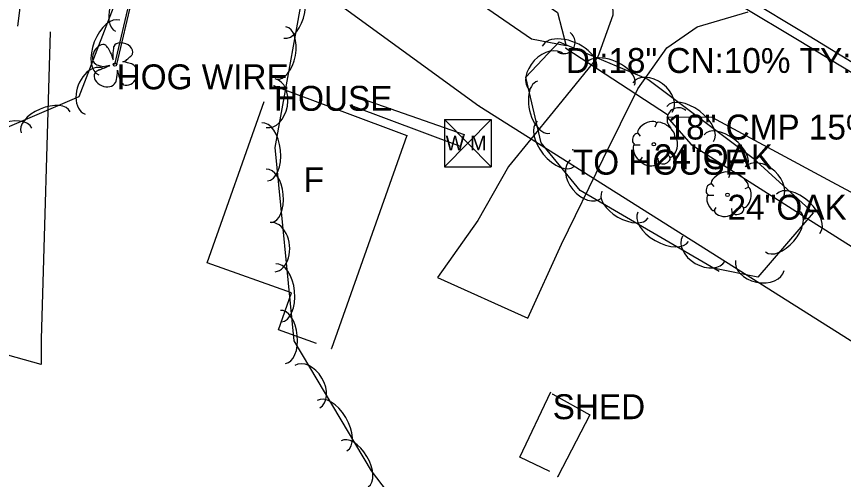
# Model space of a CAD drawing. Extents: x 1441650 to 1491889, y 345904 to 358319.
# Drawn here: x 1445119.8 to 1445285.8, y 354726 to 354818.8 of the extents above; entities that cross this region are included whole.
import ezdxf

# ---------------------------------------------------------------- set-up
doc = ezdxf.new("R2010")
doc.units = 0
for name, color, linetype in [('S_BUILDING', 7, 'Continuous'), ('S_BUILDING_ANNOT', 7, 'Continuous'), ('S_CROSS_DRAIN', 7, 'Continuous'), ('S_CROSS_DRAIN_ANNOT', 7, 'Continuous'), ('S_DITCHLINE', 7, 'Continuous'), ('S_DRG_PT_SYM', 7, 'Continuous'), ('S_EDGE_PAVEMENT', 7, 'Continuous'), ('S_FENCE', 7, 'Continuous'), ('S_FENCE_ANNOT', 7, 'Continuous'), ('S_GRAVEL_ROAD', 7, 'Continuous'), ('S_MSC_PT_SYM', 7, 'Continuous'), ('S_PARKING', 7, 'Continuous'), ('S_SHOULDER', 7, 'Continuous'), ('S_SIDEWALK', 7, 'Continuous'), ('S_STR_PT_SYM', 7, 'Continuous'), ('S_SURVEY_TEXT_ANNOT', 7, 'Continuous'), ('S_TREE', 7, 'Continuous'), ('S_TREE_ANNOT', 7, 'Continuous'), ('S_UTL_PT_SYM', 7, 'Continuous'), ('S_WATER_UTILITIES', 7, 'Continuous')]:
    doc.layers.add(name, color=color, linetype=linetype)

msp = doc.modelspace()

# ---------------------------------------------------------------- linework, layer by layer
at = {"layer": 'S_BUILDING'}
for p, q in [((1445171.46, 354804.91), (1445198.16, 354794.96)), ((1445198.16, 354794.96), (1445183.03, 354752.26)), ((1445227.42, 354743.05), (1445234.89, 354738.9)), ((1445234.89, 354738.9), (1445228.42, 354726.52))]:
    msp.add_line(p, q, dxfattribs=at)
for points in [[(1445179.98, 354753.26), (1445172.35, 354755.96), (1445174.99, 354763.4), (1445158.04, 354769.4), (1445169.51, 354801.81)], [(1445226.82, 354727.56), (1445220.79, 354730.44), (1445227.05, 354743.55)]]:
    msp.add_lwpolyline(points, dxfattribs=at)
at = {"layer": 'S_CROSS_DRAIN'}
msp.add_line((1445230.06, 354812.5), (1445250.49, 354799.15), dxfattribs=at)
for centre, start, end in [((1445229.64, 354813.68), 236.3419, 56.6711), ((1445252.68, 354798.21), 50.5486, 230.8777)]:
    msp.add_arc(centre, 2.3, start, end, dxfattribs=at)
at = {"layer": 'S_DITCHLINE'}
msp.add_lwpolyline([(1445133.69, 354878.31), (1445145.12, 354876.22), (1445156.65, 354868.46), (1445168.18, 354860.69), (1445179.71, 354852.93), (1445191.24, 354845.17), (1445209.83, 354832.39), (1445228.41, 354819.61), (1445230.13, 354812.91), (1445223.16, 354814.25), (1445205.4, 354826.54), (1445187.64, 354838.83), (1445175.09, 354847.2), (1445162.53, 354855.58), (1445149.98, 354863.95), (1445137.42, 354872.33)], close=True, dxfattribs=at)
for points in [[(1445250.37, 354798.73), (1445259.4, 354798.62), (1445271.46, 354792.13), (1445283.51, 354785.64), (1445295.57, 354779.15), (1445307.62, 354772.66), (1445328.21, 354760.56), (1445348.8, 354748.46), (1445369.38, 354736.36), (1445389.97, 354724.26), (1445403.57, 354716.68), (1445417.17, 354709.1), (1445430.78, 354701.52), (1445444.38, 354693.94), (1445450.39, 354687.52), (1445454.25, 354683.19)], [(1445250.37, 354798.73), (1445255.23, 354793.12), (1445266.85, 354785.74), (1445278.47, 354778.37), (1445290.09, 354771), (1445301.71, 354763.63), (1445322.84, 354752.21), (1445343.98, 354740.8), (1445365.12, 354729.38), (1445386.26, 354717.97), (1445400.04, 354710.57), (1445413.83, 354703.16), (1445427.62, 354695.76), (1445441.41, 354688.36), (1445449.06, 354684.91), (1445454.1, 354683.1)]]:
    msp.add_lwpolyline(points, dxfattribs=at)
at = {"layer": 'S_DRG_PT_SYM'}
for points in [[(1445230.06, 354812.5), (1445230.06, 354812.55), (1445230.06, 354812.5), (1445230.01, 354812.5), (1445230.06, 354812.5), (1445230.06, 354812.45), (1445230.06, 354812.5), (1445230.11, 354812.5)], [(1445250.49, 354799.15), (1445250.49, 354799.2), (1445250.49, 354799.15), (1445250.44, 354799.15), (1445250.49, 354799.15), (1445250.49, 354799.1), (1445250.49, 354799.15), (1445250.54, 354799.15)]]:
    msp.add_lwpolyline(points, dxfattribs=at)
at = {"layer": 'S_EDGE_PAVEMENT'}
msp.add_lwpolyline([(1445104.48, 354931.44), (1445117.54, 354922.02), (1445130.6, 354912.6), (1445144.39, 354902.99), (1445158.18, 354893.39), (1445171.35, 354884.38), (1445184.53, 354875.37), (1445198.09, 354866.37), (1445211.64, 354857.38), (1445224.35, 354849.14), (1445237.06, 354840.89), (1445251.76, 354831.71), (1445266.45, 354822.53), (1445278.03, 354815.47), (1445289.61, 354808.41)], dxfattribs=at)
at = {"layer": 'S_FENCE'}
msp.add_line((1445139.86, 354809.22), (1445149.39, 354849.44), dxfattribs=at)
at = {"layer": 'S_GRAVEL_ROAD'}
for points in [[(1445145.25, 354898.26), (1445134.77, 354893.19), (1445128.47, 354882.68), (1445125.02, 354867.07), (1445123.61, 354846.52), (1445123.67, 354846.62), (1445121.82, 354831.77), (1445119.97, 354816.92)], [(1445240.23, 354836.51), (1445239.23, 354827.85), (1445239.49, 354819.07), (1445236.48, 354810.72), (1445227.52, 354799.71), (1445218.56, 354788.71), (1445212.4, 354777.92), (1445204.27, 354766.46), (1445222.43, 354758.3), (1445229.22, 354773.13), (1445237.54, 354790.26), (1445244.54, 354804.35), (1445250.33, 354812.56), (1445256.45, 354816.73), (1445266.68, 354819.75)]]:
    msp.add_lwpolyline(points, dxfattribs=at)
at = {"layer": 'S_MSC_PT_SYM'}
for points in [[(1445139.86, 354809.22), (1445139.86, 354809.27), (1445139.86, 354809.22), (1445139.81, 354809.22), (1445139.86, 354809.22), (1445139.86, 354809.17), (1445139.86, 354809.22), (1445139.91, 354809.22)], [(1445231.48, 354792.1), (1445231.48, 354792.15), (1445231.48, 354792.1), (1445231.43, 354792.1), (1445231.48, 354792.1), (1445231.48, 354792.05), (1445231.48, 354792.1), (1445231.53, 354792.1)]]:
    msp.add_lwpolyline(points, dxfattribs=at)
at = {"layer": 'S_PARKING'}
msp.add_lwpolyline([(1445126.52, 354815.76), (1445124.68, 354754.11), (1445124.67, 354749.01), (1445097.1, 354756.74), (1445108.92, 354816.29)], dxfattribs=at)
at = {"layer": 'S_SHOULDER'}
msp.add_lwpolyline([(1445103.05, 354930.2), (1445116.32, 354920.82), (1445129.59, 354911.44), (1445143.44, 354901.68), (1445157.3, 354891.92), (1445170.43, 354883.05), (1445183.57, 354874.18), (1445197.06, 354865.12), (1445210.55, 354856.07), (1445223.33, 354847.89), (1445236.12, 354839.71), (1445250.59, 354830.39), (1445265.05, 354821.07), (1445276.89, 354813.98), (1445288.72, 354806.89)], dxfattribs=at)
at = {"layer": 'S_SIDEWALK'}
msp.add_lwpolyline([(1445188, 354802.74), (1445209.64, 354795.15), (1445208.88, 354792.73), (1445186.86, 354800.99)], dxfattribs=at)
at = {"layer": 'S_STR_PT_SYM'}
for points in [[(1445171.46, 354804.91), (1445171.46, 354804.96), (1445171.46, 354804.91), (1445171.41, 354804.91), (1445171.46, 354804.91), (1445171.46, 354804.86), (1445171.46, 354804.91), (1445171.51, 354804.91)], [(1445198.16, 354794.96), (1445198.16, 354795.01), (1445198.16, 354794.96), (1445198.11, 354794.96), (1445198.16, 354794.96), (1445198.16, 354794.91), (1445198.16, 354794.96), (1445198.21, 354794.96)], [(1445183.03, 354752.26), (1445183.03, 354752.31), (1445183.03, 354752.26), (1445182.98, 354752.26), (1445183.03, 354752.26), (1445183.03, 354752.21), (1445183.03, 354752.26), (1445183.08, 354752.26)], [(1445227.42, 354743.05), (1445227.42, 354743.1), (1445227.42, 354743.05), (1445227.37, 354743.05), (1445227.42, 354743.05), (1445227.42, 354743), (1445227.42, 354743.05), (1445227.47, 354743.05)], [(1445234.89, 354738.9), (1445234.89, 354738.95), (1445234.89, 354738.9), (1445234.84, 354738.9), (1445234.89, 354738.9), (1445234.89, 354738.85), (1445234.89, 354738.9), (1445234.94, 354738.9)], [(1445228.42, 354726.52), (1445228.42, 354726.57), (1445228.42, 354726.52), (1445228.37, 354726.52), (1445228.42, 354726.52), (1445228.42, 354726.47), (1445228.42, 354726.52), (1445228.47, 354726.52)]]:
    msp.add_lwpolyline(points, dxfattribs=at)
at = {"layer": 'S_TREE'}
for p, q in [((1445139.51, 354809.19), (1445149.76, 354852.91)), ((1445139.14, 354810.17), (1445138.89, 354811.06)), ((1445141.09, 354809.71), (1445141.46, 354809.87)), ((1445138.49, 354809), (1445137.51, 354808.79)), ((1445140.02, 354808.07), (1445140.1, 354807.63)), ((1445248.29, 354797.45), (1445247.9, 354796.6)), ((1445244.49, 354795.43), (1445244.99, 354794.85)), ((1445251.85, 354794.66), (1445251.19, 354794.39)), ((1445243.83, 354793.11), (1445244.96, 354793.11)), ((1445244.99, 354789.93), (1445245.46, 354790.63)), ((1445248.68, 354789.66), (1445248.6, 354790.43)), ((1445251.08, 354790.55), (1445250.61, 354790.98)), ((1445263.08, 354787.3), (1445262.7, 354786.45)), ((1445259.29, 354785.29), (1445259.79, 354784.71)), ((1445258.63, 354782.96), (1445259.75, 354782.96)), ((1445266.65, 354784.51), (1445265.99, 354784.24)), ((1445259.79, 354779.78), (1445260.25, 354780.48)), ((1445263.47, 354779.51), (1445263.39, 354780.29)), ((1445265.87, 354780.4), (1445265.41, 354780.83))]:
    msp.add_line(p, q, dxfattribs=at)
for points in [[(1445062.66, 354737.7), (1445036.25, 354743.75), (1445018.34, 354758.77), (1445002, 354780.57), (1445008.72, 354803.48), (1445034.19, 354809.69), (1445078.19, 354795.67), (1445109.88, 354793.21), (1445132.32, 354802.76), (1445141.03, 354825.37), (1445149.69, 354845.03), (1445168.23, 354849.09), (1445178.41, 354829.92), (1445171.6, 354792.55), (1445175.47, 354753.75), (1445190.97, 354727.66), (1445216.54, 354694.19), (1445235.93, 354674.69), (1445255.34, 354667.34), (1445272.22, 354672.85), (1445290.88, 354695.22)], [(1445260.86, 354767.7), (1445232.91, 354783.89), (1445225.09, 354793.51), (1445222, 354806.68), (1445228.71, 354813.75), (1445246.52, 354806.26), (1445267.67, 354790.38), (1445279.7, 354779.41), (1445268.6, 354766.52), (1445259.98, 354768.27)]]:
    msp.add_lwpolyline(points, dxfattribs=at)
for centre in [(1445139.51, 354809.19), (1445247.73, 354793.2), (1445262.53, 354783.06)]:
    msp.add_circle(centre, 0.341, dxfattribs=at)
for centre, major_axis, ratio, start_param, end_param in [((1445141.57, 354820.86), (-1.92, -4.99), 0.540597, 3.141377, 6.282969), ((1445174.49, 354820.24), (1.05, 5.77), 0.549958, 3.141593, 6.283185), ((1445138.38, 354812.58), (-2.11, -5.48), 0.549976, 3.14137, 6.282962), ((1445172.9, 354811.52), (0.96, 5.26), 0.54058, 3.141593, 6.283185), ((1445230.74, 354810.59), (-5.41, 2.28), 0.55008, 3.141592, 6.283185), ((1445136.62, 354811.21), (-1.03, -1.88), 0.662338, 3.141593, 6.283185), ((1445138.27, 354812.07), (0.62, -1.01), 0.083512, 0, 3.141593), ((1445139.21, 354811.49), (-0.07, -1.33), 0.068203, 3.141593, 6.283185), ((1445141.17, 354812.07), (1.89, -0.74), 0.673998, 0, 3.141593), ((1445142.26, 354810.6), (-0.798, -0.73), 0.092159, 0, 3.141593), ((1445226.2, 354807.65), (-3.41, -3.6), 0.685311, 3.141593, 6.283185), ((1445142.05, 354809.48), (0.96, -0.23), 0.056001, 0, 3.141593), ((1445238.92, 354807.15), (-4.93, 2.07), 0.540699, 3.141592, 6.283185), ((1445135.3, 354803.85), (-1.78, -4.62), 0.685181, 3.141227, 6.28282), ((1445135.93, 354807.79), (0.477, 0.328), 0.136309, 0, 3.141593), ((1445136.55, 354809.05), (0.964, -0.267), 0.113563, 3.141593, 6.283185), ((1445137.45, 354808.56), (1.04, 0.44), 0.002756, 3.141593, 6.283185), ((1445139.79, 354806.91), (0.19, 1.31), 0.114148, 3.141593, 5.822668), ((1445142.12, 354807.2), (0.88, 2.05), 0.81717, 3.141593, 6.283185), ((1445137.53, 354806.53), (2.07, -0.93), 0.760068, 3.141593, 6.283185), ((1445140.36, 354806.86), (0.254, -0.771), 0.051603, 3.141593, 6.283185), ((1445170.8, 354801.43), (0.89, 4.87), 0.685159, 3.141593, 6.283185), ((1445247.45, 354802.58), (-3.96, 2.97), 0.685311, 3.141593, 6.283185), ((1445140.93, 354805.63), (-0.321, 0.467), 0.094289, 0, 3.141593), ((1445225.6, 354800.63), (1.22, -5.2), 0.5407, 3.141592, 6.283185), ((1445125.6, 354797.59), (-4.92, -2.09), 0.540568, 3.141593, 6.283185), ((1445255.01, 354797.24), (-4.69, 3.52), 0.55008, 3.141593, 6.283185), ((1445117.44, 354794.12), (-5.4, -2.3), 0.549946, 3.141593, 6.283185), ((1445246.39, 354796.41), (1.86, 1.08), 0.471018, 0, 3.141593), ((1445250.05, 354796.08), (-1.81, 1.36), 0.405113, 3.141593, 6.283186), ((1445169.56, 354791.67), (-0.58, 5.84), 0.550016, 3.141686, 6.283278), ((1445228.03, 354793.26), (3.7, -4.55), 0.55008, 3.141593, 6.283185), ((1445262.1, 354791.91), (-4.28, 3.21), 0.540699, 3.141593, 6.283185), ((1445244.16, 354794.29), (0.31, 1.03), 0.646762, 0, 3.141593), ((1445251.4, 354792.67), (0.46, 2.04), 0.482994, 3.141593, 6.283185), ((1445244.46, 354791.64), (-0.61, 1.6), 0.420543, 6.283185, 9.424777), ((1445234.08, 354786.24), (3.13, -3.84), 0.685311, 3.141593, 6.283185), ((1445246.93, 354789.86), (-1.83, 0.19), 0.529943, 0, 3.141593), ((1445249.88, 354790.15), (1.09, 0.46), 0.711534, 3.141592, 6.283185), ((1445269.71, 354785.3), (-3.66, 3.34), 0.685311, 3.141593, 6.283185), ((1445170.44, 354782.85), (-0.53, 5.32), 0.540637, 3.141683, 6.283275), ((1445261.19, 354786.26), (1.86, 1.08), 0.471018, 0, 3.141593), ((1445264.84, 354785.94), (-1.81, 1.36), 0.405113, 3.141593, 6.283186), ((1445258.95, 354784.14), (0.31, 1.03), 0.646762, 0, 3.141593), ((1445266.2, 354782.53), (0.46, 2.04), 0.482994, 3.141593, 6.283185), ((1445241.95, 354781.11), (4.63, -2.68), 0.540699, 3.141593, 6.283185), ((1445259.26, 354781.49), (-0.61, 1.6), 0.420543, 6.283185, 9.424777), ((1445276.73, 354779.26), (-4.34, 3.95), 0.55008, 3.141593, 6.283185), ((1445249.62, 354776.66), (5.08, -2.94), 0.55008, 3.141593, 6.283185), ((1445261.72, 354779.71), (-1.83, 0.19), 0.529943, 0, 3.141593), ((1445264.68, 354780.01), (1.09, 0.46), 0.711534, 3.141592, 6.283185), ((1445273.67, 354775.66), (3.49, 4.05), 0.540699, 3.141593, 6.283185), ((1445171.2, 354772.57), (-0.49, 4.93), 0.685232, 3.141745, 6.283338), ((1445257.76, 354772.25), (4.29, -2.48), 0.685311, 3.141593, 6.283185), ((1445269.02, 354768.86), (4.86, -0.99), 0.685311, 3.141593, 6.283185), ((1445172.38, 354763.39), (-0.58, 5.84), 0.550016, 3.141686, 6.283278), ((1445173.26, 354754.56), (-0.53, 5.32), 0.540637, 3.141683, 6.283275), ((1445178.16, 354744.56), (-2.53, 4.26), 0.685291, 3.141593, 6.283185), ((1445183.11, 354736.74), (-3, 5.05), 0.550064, 3.141593, 6.283185), ((1445187.64, 354729.11), (-2.73, 4.6), 0.540684, 3.141593, 6.283185)]:
    msp.add_ellipse(centre, major_axis=major_axis, ratio=ratio, start_param=start_param, end_param=end_param, dxfattribs=at)
at = {"layer": 'S_UTL_PT_SYM'}
msp.add_lwpolyline([(1445212.56, 354800.91), (1445212.56, 354800.96), (1445212.56, 354800.91), (1445212.51, 354800.91), (1445212.56, 354800.91), (1445212.56, 354800.86), (1445212.56, 354800.91), (1445212.61, 354800.91)], dxfattribs=at)
at = {"layer": 'S_WATER_UTILITIES'}
for p, q in [((1444933.86, 355003.67), (1445212.56, 354800.91)), ((1445212.56, 354800.91), (1445328.49, 354727.82)), ((1445205.72, 354798.18), (1445215.06, 354798.18)), ((1445205.72, 354798.18), (1445205.72, 354788.69)), ((1445205.72, 354798.18), (1445215.06, 354788.69)), ((1445215.06, 354798.18), (1445205.72, 354788.69)), ((1445215.06, 354798.18), (1445215.06, 354788.69)), ((1445205.72, 354788.69), (1445215.06, 354788.69))]:
    msp.add_line(p, q, dxfattribs=at)

# ---------------------------------------------------------------- texts
at = {"layer": 'S_BUILDING_ANNOT'}
for s, p in [('HOUSE', (1445171.46, 354799.91)), ('F', (1445177.4, 354783.6)), ('SHED', (1445227.42, 354738.05))]:
    msp.add_text(s, height=5, dxfattribs=at).set_placement(p)
at = {"layer": 'S_CROSS_DRAIN_ANNOT'}
for s, p in [('DI:18" CN:10% TY:CMP', (1445230.06, 354807.5)), ('18" CMP 15% FILL', (1445250.49, 354794.15))]:
    msp.add_text(s, height=5, dxfattribs=at).set_placement(p)
at = {"layer": 'S_FENCE_ANNOT'}
msp.add_text('HOG WIRE', height=5, dxfattribs=at).set_placement((1445139.86, 354804.22))
at = {"layer": 'S_SURVEY_TEXT_ANNOT'}
msp.add_text('TO HOUSE', height=5, dxfattribs=at).set_placement((1445231.48, 354787.1))
at = {"layer": 'S_TREE_ANNOT'}
for p in [(1445247.73, 354788.2), (1445262.53, 354778.06)]:
    msp.add_text('24"OAK', height=5, dxfattribs=at).set_placement(p)
at = {"layer": 'S_WATER_UTILITIES'}
msp.add_text('W M', height=3, rotation=360, dxfattribs=at).set_placement((1445205.92, 354791.95))

doc.saveas('drawing.dxf')
